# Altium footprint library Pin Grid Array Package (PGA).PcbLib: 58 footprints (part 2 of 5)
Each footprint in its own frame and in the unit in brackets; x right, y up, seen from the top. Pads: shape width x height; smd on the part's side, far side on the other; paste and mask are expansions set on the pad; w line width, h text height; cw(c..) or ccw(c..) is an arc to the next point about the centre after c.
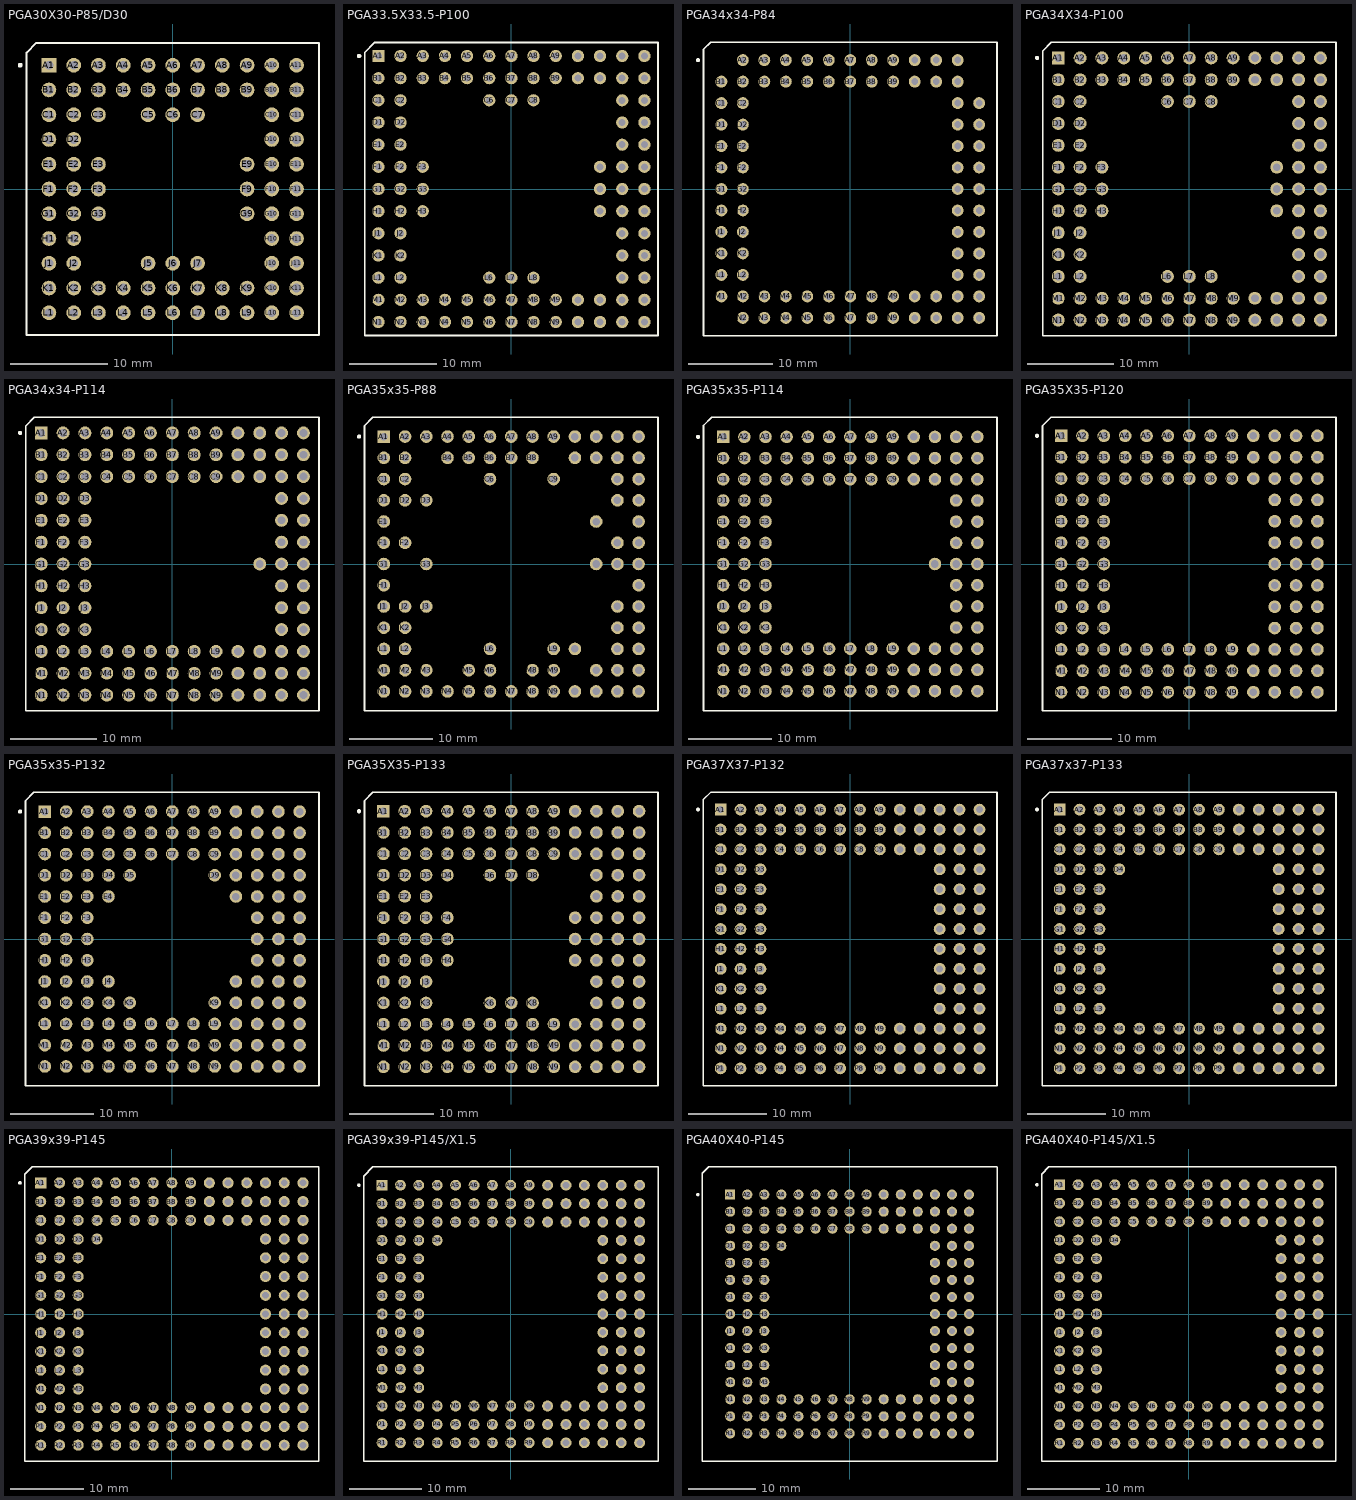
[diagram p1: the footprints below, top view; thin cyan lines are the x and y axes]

## PGA30X30-P85/D30 [mm]
pads (85):
  rect 1.5x1.5 hole 0.9: A1(-12.7,12.7)
  round 1.5 hole 0.9: A2(-10.16,12.7) A3(-7.62,12.7) A4(-5.08,12.7) A5(-2.54,12.7) A6(0,12.7) A7(2.54,12.7) A8(5.08,12.7) A9(7.62,12.7) A10(10.16,12.7) A11(12.7,12.7) B1(-12.7,10.16) B2(-10.16,10.16) B3(-7.62,10.16) B4(-5.08,10.16) B5(-2.54,10.16) B6(0,10.16) B7(2.54,10.16) B8(5.08,10.16) B9(7.62,10.16) B10(10.16,10.16) B11(12.7,10.16) C1(-12.7,7.62) C2(-10.16,7.62) C3(-7.62,7.62) C5(-2.54,7.62) C6(0,7.62) C7(2.54,7.62) C10(10.16,7.62) C11(12.7,7.62) D1(-12.7,5.08) D2(-10.16,5.08) D10(10.16,5.08) D11(12.7,5.08) E1(-12.7,2.54) E2(-10.16,2.54) E3(-7.62,2.54) E9(7.62,2.54) E10(10.16,2.54) E11(12.7,2.54) F1(-12.7,0) F2(-10.16,0) F3(-7.62,0) F9(7.62,0) F10(10.16,0) F11(12.7,0) G1(-12.7,-2.54) G2(-10.16,-2.54) G3(-7.62,-2.54) G9(7.62,-2.54) G10(10.16,-2.54) G11(12.7,-2.54) H1(-12.7,-5.08) H2(-10.16,-5.08) H10(10.16,-5.08) H11(12.7,-5.08) J1(-12.7,-7.62) J2(-10.16,-7.62) J5(-2.54,-7.62) J6(0,-7.62) J7(2.54,-7.62) J10(10.16,-7.62) J11(12.7,-7.62) K1(-12.7,-10.16) K2(-10.16,-10.16) K3(-7.62,-10.16) K4(-5.08,-10.16) K5(-2.54,-10.16) K6(0,-10.16) K7(2.54,-10.16) K8(5.08,-10.16) K9(7.62,-10.16) K10(10.16,-10.16) K11(12.7,-10.16) L1(-12.7,-12.7) L2(-10.16,-12.7) L3(-7.62,-12.7) L4(-5.08,-12.7) L5(-2.54,-12.7) L6(0,-12.7) L7(2.54,-12.7) L8(5.08,-12.7) L9(7.62,-12.7) L10(10.16,-12.7) L11(12.7,-12.7)
Top Overlay:
  circle w0.25: c-15.65,12.7 r0.125
  lines w0.2: -15,-15 -15,14 -14,15 15,15 15,-15 -15,-15

## PGA33.5X33.5-P100 [mm]
pads (100):
  rect 1.4x1.4 hole 0.8: A1(-15.24,15.24)
  round 1.4 hole 0.8: A2(-12.7,15.24) A3(-10.16,15.24) A4(-7.62,15.24) A5(-5.08,15.24) A6(-2.54,15.24) A7(0,15.24) A8(2.54,15.24) A9(5.08,15.24) A10(7.62,15.24) A11(10.16,15.24) A12(12.7,15.24) A13(15.24,15.24) B1(-15.24,12.7) B2(-12.7,12.7) B3(-10.16,12.7) B4(-7.62,12.7) B5(-5.08,12.7) B6(-2.54,12.7) B7(0,12.7) B8(2.54,12.7) B9(5.08,12.7) B10(7.62,12.7) B11(10.16,12.7) B12(12.7,12.7) B13(15.24,12.7) C1(-15.24,10.16) C2(-12.7,10.16) C6(-2.54,10.16) C7(0,10.16) C8(2.54,10.16) C12(12.7,10.16) C13(15.24,10.16) D1(-15.24,7.62) D2(-12.7,7.62) D12(12.7,7.62) D13(15.24,7.62) E1(-15.24,5.08) E2(-12.7,5.08) E12(12.7,5.08) E13(15.24,5.08) F1(-15.24,2.54) F2(-12.7,2.54) F3(-10.16,2.54) F11(10.16,2.54) F12(12.7,2.54) F13(15.24,2.54) G1(-15.24,0) G2(-12.7,0) G3(-10.16,0) G11(10.16,0) G12(12.7,0) G13(15.24,0) H1(-15.24,-2.54) H2(-12.7,-2.54) H3(-10.16,-2.54) H11(10.16,-2.54) H12(12.7,-2.54) H13(15.24,-2.54) J1(-15.24,-5.08) J2(-12.7,-5.08) J12(12.7,-5.08) J13(15.24,-5.08) K1(-15.24,-7.62) K2(-12.7,-7.62) K12(12.7,-7.62) K13(15.24,-7.62) L1(-15.24,-10.16) L2(-12.7,-10.16) L6(-2.54,-10.16) L7(0,-10.16) L8(2.54,-10.16) L12(12.7,-10.16) L13(15.24,-10.16) M1(-15.24,-12.7) M2(-12.7,-12.7) M3(-10.16,-12.7) M4(-7.62,-12.7) M5(-5.08,-12.7) M6(-2.54,-12.7) M7(0,-12.7) M8(2.54,-12.7) M9(5.08,-12.7) M10(7.62,-12.7) M11(10.16,-12.7) M12(12.7,-12.7) M13(15.24,-12.7) N1(-15.24,-15.24) N2(-12.7,-15.24) N3(-10.16,-15.24) N4(-7.62,-15.24) N5(-5.08,-15.24) N6(-2.54,-15.24) N7(0,-15.24) N8(2.54,-15.24) N9(5.08,-15.24) N10(7.62,-15.24) N11(10.16,-15.24) N12(12.7,-15.24) N13(15.24,-15.24)
Top Overlay:
  circle w0.25: c-17.45,15.24 r0.125
  lines w0.2: -16.8,-16.8 -16.8,15.646 -15.646,16.8 16.8,16.8 16.8,-16.8 -16.8,-16.8

## PGA34x34-P84 [mm]
pads (84):
  round 1.4 hole 0.8: A2(-12.7,15.24) A3(-10.16,15.24) A4(-7.62,15.24) A5(-5.08,15.24) A6(-2.54,15.24) A7(0,15.24) A8(2.54,15.24) A9(5.08,15.24) A10(7.62,15.24) A11(10.16,15.24) A12(12.7,15.24) B1(-15.24,12.7) B2(-12.7,12.7) B3(-10.16,12.7) B4(-7.62,12.7) B5(-5.08,12.7) B6(-2.54,12.7) B7(0,12.7) B8(2.54,12.7) B9(5.08,12.7) B10(7.62,12.7) B11(10.16,12.7) B12(12.7,12.7) C1(-15.24,10.16) C2(-12.7,10.16) C12(12.7,10.16) C13(15.24,10.16) D1(-15.24,7.62) D2(-12.7,7.62) D12(12.7,7.62) D13(15.24,7.62) E1(-15.24,5.08) E2(-12.7,5.08) E12(12.7,5.08) E13(15.24,5.08) F1(-15.24,2.54) F2(-12.7,2.54) F12(12.7,2.54) F13(15.24,2.54) G1(-15.24,0) G2(-12.7,0) G12(12.7,0) G13(15.24,0) H1(-15.24,-2.54) H2(-12.7,-2.54) H12(12.7,-2.54) H13(15.24,-2.54) J1(-15.24,-5.08) J2(-12.7,-5.08) J12(12.7,-5.08) J13(15.24,-5.08) K1(-15.24,-7.62) K2(-12.7,-7.62) K12(12.7,-7.62) K13(15.24,-7.62) L1(-15.24,-10.16) L2(-12.7,-10.16) L12(12.7,-10.16) L13(15.24,-10.16) M1(-15.24,-12.7) M2(-12.7,-12.7) M3(-10.16,-12.7) M4(-7.62,-12.7) M5(-5.08,-12.7) M6(-2.54,-12.7) M7(0,-12.7) M8(2.54,-12.7) M9(5.08,-12.7) M10(7.62,-12.7) M11(10.16,-12.7) M12(12.7,-12.7) M13(15.24,-12.7) N2(-12.7,-15.24) N3(-10.16,-15.24) N4(-7.62,-15.24) N5(-5.08,-15.24) N6(-2.54,-15.24) N7(0,-15.24) N8(2.54,-15.24) N9(5.08,-15.24) N10(7.62,-15.24) N11(10.16,-15.24) N12(12.7,-15.24) N13(15.24,-15.24)
Top Overlay:
  circle w0.25: c-18,15.24 r0.125
  lines w0.2: -17.35,-17.35 17.35,-17.35 17.35,17.35 -16.51,17.35 -17.35,16.51 -17.35,-17.35

## PGA34X34-P100 [mm]
pads (100):
  rect 1.5x1.5 hole 0.9: A1(-15.24,15.24)
  round 1.5 hole 0.9: A2(-12.7,15.24) A3(-10.16,15.24) A4(-7.62,15.24) A5(-5.08,15.24) A6(-2.54,15.24) A7(0,15.24) A8(2.54,15.24) A9(5.08,15.24) A10(7.62,15.24) A11(10.16,15.24) A12(12.7,15.24) A13(15.24,15.24) B1(-15.24,12.7) B2(-12.7,12.7) B3(-10.16,12.7) B4(-7.62,12.7) B5(-5.08,12.7) B6(-2.54,12.7) B7(0,12.7) B8(2.54,12.7) B9(5.08,12.7) B10(7.62,12.7) B11(10.16,12.7) B12(12.7,12.7) B13(15.24,12.7) C1(-15.24,10.16) C2(-12.7,10.16) C6(-2.54,10.16) C7(0,10.16) C8(2.54,10.16) C12(12.7,10.16) C13(15.24,10.16) D1(-15.24,7.62) D2(-12.7,7.62) D12(12.7,7.62) D13(15.24,7.62) E1(-15.24,5.08) E2(-12.7,5.08) E12(12.7,5.08) E13(15.24,5.08) F1(-15.24,2.54) F2(-12.7,2.54) F3(-10.16,2.54) F11(10.16,2.54) F12(12.7,2.54) F13(15.24,2.54) G1(-15.24,0) G2(-12.7,0) G3(-10.16,0) G11(10.16,0) G12(12.7,0) G13(15.24,0) H1(-15.24,-2.54) H2(-12.7,-2.54) H3(-10.16,-2.54) H11(10.16,-2.54) H12(12.7,-2.54) H13(15.24,-2.54) J1(-15.24,-5.08) J2(-12.7,-5.08) J12(12.7,-5.08) J13(15.24,-5.08) K1(-15.24,-7.62) K2(-12.7,-7.62) K12(12.7,-7.62) K13(15.24,-7.62) L1(-15.24,-10.16) L2(-12.7,-10.16) L6(-2.54,-10.16) L7(0,-10.16) L8(2.54,-10.16) L12(12.7,-10.16) L13(15.24,-10.16) M1(-15.24,-12.7) M2(-12.7,-12.7) M3(-10.16,-12.7) M4(-7.62,-12.7) M5(-5.08,-12.7) M6(-2.54,-12.7) M7(0,-12.7) M8(2.54,-12.7) M9(5.08,-12.7) M10(7.62,-12.7) M11(10.16,-12.7) M12(12.7,-12.7) M13(15.24,-12.7) N1(-15.24,-15.24) N2(-12.7,-15.24) N3(-10.16,-15.24) N4(-7.62,-15.24) N5(-5.08,-15.24) N6(-2.54,-15.24) N7(0,-15.24) N8(2.54,-15.24) N9(5.08,-15.24) N10(7.62,-15.24) N11(10.16,-15.24) N12(12.7,-15.24) N13(15.24,-15.24)
Top Overlay:
  circle w0.25: c-17.7,15.24 r0.125
  lines w0.2: -17.05,-17.05 -17.05,16.05 -16.05,17.05 17.05,17.05 17.05,-17.05 -17.05,-17.05

## PGA34x34-P114 [mm]
pads (114):
  rect 1.5x1.5 hole 0.9: A1(-15.24,15.24)
  round 1.5 hole 0.9: A2(-12.7,15.24) A3(-10.16,15.24) A4(-7.62,15.24) A5(-5.08,15.24) A6(-2.54,15.24) A7(0,15.24) A8(2.54,15.24) A9(5.08,15.24) A10(7.62,15.24) A11(10.16,15.24) A12(12.7,15.24) A13(15.24,15.24) B1(-15.24,12.7) B2(-12.7,12.7) B3(-10.16,12.7) B4(-7.62,12.7) B5(-5.08,12.7) B6(-2.54,12.7) B7(0,12.7) B8(2.54,12.7) B9(5.08,12.7) B10(7.62,12.7) B11(10.16,12.7) B12(12.7,12.7) B13(15.24,12.7) C1(-15.24,10.16) C2(-12.7,10.16) C3(-10.16,10.16) C4(-7.62,10.16) C5(-5.08,10.16) C6(-2.54,10.16) C7(0,10.16) C8(2.54,10.16) C9(5.08,10.16) C10(7.62,10.16) C11(10.16,10.16) C12(12.7,10.16) C13(15.24,10.16) D1(-15.24,7.62) D2(-12.7,7.62) D3(-10.16,7.62) D12(12.7,7.62) D13(15.24,7.62) E1(-15.24,5.08) E2(-12.7,5.08) E3(-10.16,5.08) E12(12.7,5.08) E13(15.24,5.08) F1(-15.24,2.54) F2(-12.7,2.54) F3(-10.16,2.54) F12(12.7,2.54) F13(15.24,2.54) G1(-15.24,0) G2(-12.7,0) G3(-10.16,0) G11(10.16,0) G12(12.7,0) G13(15.24,0) H1(-15.24,-2.54) H2(-12.7,-2.54) H3(-10.16,-2.54) H12(12.7,-2.54) H13(15.24,-2.54) J1(-15.24,-5.08) J2(-12.7,-5.08) J3(-10.16,-5.08) J12(12.7,-5.08) J13(15.24,-5.08) K1(-15.24,-7.62) K2(-12.7,-7.62) K3(-10.16,-7.62) K12(12.7,-7.62) K13(15.24,-7.62) L1(-15.24,-10.16) L2(-12.7,-10.16) L3(-10.16,-10.16) L4(-7.62,-10.16) L5(-5.08,-10.16) L6(-2.54,-10.16) L7(0,-10.16) L8(2.54,-10.16) L9(5.08,-10.16) L10(7.62,-10.16) L11(10.16,-10.16) L12(12.7,-10.16) L13(15.24,-10.16) M1(-15.24,-12.7) M2(-12.7,-12.7) M3(-10.16,-12.7) M4(-7.62,-12.7) M5(-5.08,-12.7) M6(-2.54,-12.7) M7(0,-12.7) M8(2.54,-12.7) M9(5.08,-12.7) M10(7.62,-12.7) M11(10.16,-12.7) M12(12.7,-12.7) M13(15.24,-12.7) N1(-15.24,-15.24) N2(-12.7,-15.24) N3(-10.16,-15.24) N4(-7.62,-15.24) N5(-5.08,-15.24) N6(-2.54,-15.24) N7(0,-15.24) N8(2.54,-15.24) N9(5.08,-15.24) N10(7.62,-15.24) N11(10.16,-15.24) N12(12.7,-15.24) N13(15.24,-15.24)
Top Overlay:
  circle w0.25: c-17.7,15.24 r0.125
  lines w0.2: -17.05,-17.05 17.05,-17.05 17.05,17.05 -16.05,17.05 -17.05,16.05 -17.05,-17.05

## PGA35x35-P88 [mm]
pads (88):
  rect 1.5x1.5 hole 0.9: A1(-15.24,15.24)
  round 1.5 hole 0.9: A2(-12.7,15.24) A3(-10.16,15.24) A4(-7.62,15.24) A5(-5.08,15.24) A6(-2.54,15.24) A7(0,15.24) A8(2.54,15.24) A9(5.08,15.24) A10(7.62,15.24) A11(10.16,15.24) A12(12.7,15.24) A13(15.24,15.24) B1(-15.24,12.7) B2(-12.7,12.7) B4(-7.62,12.7) B5(-5.08,12.7) B6(-2.54,12.7) B7(0,12.7) B8(2.54,12.7) B10(7.62,12.7) B11(10.16,12.7) B12(12.7,12.7) B13(15.24,12.7) C1(-15.24,10.16) C2(-12.7,10.16) C6(-2.54,10.16) C9(5.08,10.16) C12(12.7,10.16) C13(15.24,10.16) D1(-15.24,7.62) D2(-12.7,7.62) D3(-10.16,7.62) D12(12.7,7.62) D13(15.24,7.62) E1(-15.24,5.08) E11(10.16,5.08) E13(15.24,5.08) F1(-15.24,2.54) F2(-12.7,2.54) F12(12.7,2.54) F13(15.24,2.54) G1(-15.24,0) G3(-10.16,0) G11(10.16,0) G12(12.7,0) G13(15.24,0) H1(-15.24,-2.54) H13(15.24,-2.54) J1(-15.24,-5.08) J2(-12.7,-5.08) J3(-10.16,-5.08) J12(12.7,-5.08) J13(15.24,-5.08) K1(-15.24,-7.62) K2(-12.7,-7.62) K12(12.7,-7.62) K13(15.24,-7.62) L1(-15.24,-10.16) L2(-12.7,-10.16) L6(-2.54,-10.16) L9(5.08,-10.16) L10(7.62,-10.16) L12(12.7,-10.16) L13(15.24,-10.16) M1(-15.24,-12.7) M2(-12.7,-12.7) M3(-10.16,-12.7) M5(-5.08,-12.7) M6(-2.54,-12.7) M8(2.54,-12.7) M9(5.08,-12.7) M11(10.16,-12.7) M12(12.7,-12.7) M13(15.24,-12.7) N1(-15.24,-15.24) N2(-12.7,-15.24) N3(-10.16,-15.24) N4(-7.62,-15.24) N5(-5.08,-15.24) N6(-2.54,-15.24) N7(0,-15.24) N8(2.54,-15.24) N9(5.08,-15.24) N10(7.62,-15.24) N11(10.16,-15.24) N12(12.7,-15.24) N13(15.24,-15.24)
Top Overlay:
  circle w0.25: c-18.2,15.24 r0.125
  lines w0.2: -17.55,-17.55 17.55,-17.55 17.55,17.55 -16.55,17.55 -17.55,16.55 -17.55,-17.55

## PGA35x35-P114 [mm]
pads (114):
  rect 1.5x1.5 hole 0.9: A1(-15.24,15.24)
  round 1.5 hole 0.9: A2(-12.7,15.24) A3(-10.16,15.24) A4(-7.62,15.24) A5(-5.08,15.24) A6(-2.54,15.24) A7(0,15.24) A8(2.54,15.24) A9(5.08,15.24) A10(7.62,15.24) A11(10.16,15.24) A12(12.7,15.24) A13(15.24,15.24) B1(-15.24,12.7) B2(-12.7,12.7) B3(-10.16,12.7) B4(-7.62,12.7) B5(-5.08,12.7) B6(-2.54,12.7) B7(0,12.7) B8(2.54,12.7) B9(5.08,12.7) B10(7.62,12.7) B11(10.16,12.7) B12(12.7,12.7) B13(15.24,12.7) C1(-15.24,10.16) C2(-12.7,10.16) C3(-10.16,10.16) C4(-7.62,10.16) C5(-5.08,10.16) C6(-2.54,10.16) C7(0,10.16) C8(2.54,10.16) C9(5.08,10.16) C10(7.62,10.16) C11(10.16,10.16) C12(12.7,10.16) C13(15.24,10.16) D1(-15.24,7.62) D2(-12.7,7.62) D3(-10.16,7.62) D12(12.7,7.62) D13(15.24,7.62) E1(-15.24,5.08) E2(-12.7,5.08) E3(-10.16,5.08) E12(12.7,5.08) E13(15.24,5.08) F1(-15.24,2.54) F2(-12.7,2.54) F3(-10.16,2.54) F12(12.7,2.54) F13(15.24,2.54) G1(-15.24,0) G2(-12.7,0) G3(-10.16,0) G11(10.16,0) G12(12.7,0) G13(15.24,0) H1(-15.24,-2.54) H2(-12.7,-2.54) H3(-10.16,-2.54) H12(12.7,-2.54) H13(15.24,-2.54) J1(-15.24,-5.08) J2(-12.7,-5.08) J3(-10.16,-5.08) J12(12.7,-5.08) J13(15.24,-5.08) K1(-15.24,-7.62) K2(-12.7,-7.62) K3(-10.16,-7.62) K12(12.7,-7.62) K13(15.24,-7.62) L1(-15.24,-10.16) L2(-12.7,-10.16) L3(-10.16,-10.16) L4(-7.62,-10.16) L5(-5.08,-10.16) L6(-2.54,-10.16) L7(0,-10.16) L8(2.54,-10.16) L9(5.08,-10.16) L10(7.62,-10.16) L11(10.16,-10.16) L12(12.7,-10.16) L13(15.24,-10.16) M1(-15.24,-12.7) M2(-12.7,-12.7) M3(-10.16,-12.7) M4(-7.62,-12.7) M5(-5.08,-12.7) M6(-2.54,-12.7) M7(0,-12.7) M8(2.54,-12.7) M9(5.08,-12.7) M10(7.62,-12.7) M11(10.16,-12.7) M12(12.7,-12.7) M13(15.24,-12.7) N1(-15.24,-15.24) N2(-12.7,-15.24) N3(-10.16,-15.24) N4(-7.62,-15.24) N5(-5.08,-15.24) N6(-2.54,-15.24) N7(0,-15.24) N8(2.54,-15.24) N9(5.08,-15.24) N10(7.62,-15.24) N11(10.16,-15.24) N12(12.7,-15.24) N13(15.24,-15.24)
Top Overlay:
  circle w0.25: c-18.25,15.24 r0.125
  lines w0.2: -17.6,-17.6 17.6,-17.6 17.6,17.6 -16.6,17.6 -17.6,16.6 -17.6,-17.6

## PGA35X35-P120 [mm]
pads (120):
  rect 1.5x1.5 hole 0.9: A1(-15.24,15.24)
  round 1.5 hole 0.9: A2(-12.7,15.24) A3(-10.16,15.24) A4(-7.62,15.24) A5(-5.08,15.24) A6(-2.54,15.24) A7(0,15.24) A8(2.54,15.24) A9(5.08,15.24) A10(7.62,15.24) A11(10.16,15.24) A12(12.7,15.24) A13(15.24,15.24) B1(-15.24,12.7) B2(-12.7,12.7) B3(-10.16,12.7) B4(-7.62,12.7) B5(-5.08,12.7) B6(-2.54,12.7) B7(0,12.7) B8(2.54,12.7) B9(5.08,12.7) B10(7.62,12.7) B11(10.16,12.7) B12(12.7,12.7) B13(15.24,12.7) C1(-15.24,10.16) C2(-12.7,10.16) C3(-10.16,10.16) C4(-7.62,10.16) C5(-5.08,10.16) C6(-2.54,10.16) C7(0,10.16) C8(2.54,10.16) C9(5.08,10.16) C10(7.62,10.16) C11(10.16,10.16) C12(12.7,10.16) C13(15.24,10.16) D1(-15.24,7.62) D2(-12.7,7.62) D3(-10.16,7.62) D11(10.16,7.62) D12(12.7,7.62) D13(15.24,7.62) E1(-15.24,5.08) E2(-12.7,5.08) E3(-10.16,5.08) E11(10.16,5.08) E12(12.7,5.08) E13(15.24,5.08) F1(-15.24,2.54) F2(-12.7,2.54) F3(-10.16,2.54) F11(10.16,2.54) F12(12.7,2.54) F13(15.24,2.54) G1(-15.24,0) G2(-12.7,0) G3(-10.16,0) G11(10.16,0) G12(12.7,0) G13(15.24,0) H1(-15.24,-2.54) H2(-12.7,-2.54) H3(-10.16,-2.54) H11(10.16,-2.54) H12(12.7,-2.54) H13(15.24,-2.54) J1(-15.24,-5.08) J2(-12.7,-5.08) J3(-10.16,-5.08) J11(10.16,-5.08) J12(12.7,-5.08) J13(15.24,-5.08) K1(-15.24,-7.62) K2(-12.7,-7.62) K3(-10.16,-7.62) K11(10.16,-7.62) K12(12.7,-7.62) K13(15.24,-7.62) L1(-15.24,-10.16) L2(-12.7,-10.16) L3(-10.16,-10.16) L4(-7.62,-10.16) L5(-5.08,-10.16) L6(-2.54,-10.16) L7(0,-10.16) L8(2.54,-10.16) L9(5.08,-10.16) L10(7.62,-10.16) L11(10.16,-10.16) L12(12.7,-10.16) L13(15.24,-10.16) M1(-15.24,-12.7) M2(-12.7,-12.7) M3(-10.16,-12.7) M4(-7.62,-12.7) M5(-5.08,-12.7) M6(-2.54,-12.7) M7(0,-12.7) M8(2.54,-12.7) M9(5.08,-12.7) M10(7.62,-12.7) M11(10.16,-12.7) M12(12.7,-12.7) M13(15.24,-12.7) N1(-15.24,-15.24) N2(-12.7,-15.24) N3(-10.16,-15.24) N4(-7.62,-15.24) N5(-5.08,-15.24) N6(-2.54,-15.24) N7(0,-15.24) N8(2.54,-15.24) N9(5.08,-15.24) N10(7.62,-15.24) N11(10.16,-15.24) N12(12.7,-15.24) N13(15.24,-15.24)
Top Overlay:
  circle w0.25: c-18.1,15.24 r0.125
  lines w0.2: -17.45,-17.45 17.45,-17.45 17.45,17.45 -16.45,17.45 -17.45,16.45 -17.45,-17.45

## PGA35x35-P132 [mm]
pads (132):
  rect 1.5x1.5 hole 0.9: A1(-15.24,15.24)
  round 1.5 hole 0.9: A2(-12.7,15.24) A3(-10.16,15.24) A4(-7.62,15.24) A5(-5.08,15.24) A6(-2.54,15.24) A7(0,15.24) A8(2.54,15.24) A9(5.08,15.24) A10(7.62,15.24) A11(10.16,15.24) A12(12.7,15.24) A13(15.24,15.24) B1(-15.24,12.7) B2(-12.7,12.7) B3(-10.16,12.7) B4(-7.62,12.7) B5(-5.08,12.7) B6(-2.54,12.7) B7(0,12.7) B8(2.54,12.7) B9(5.08,12.7) B10(7.62,12.7) B11(10.16,12.7) B12(12.7,12.7) B13(15.24,12.7) C1(-15.24,10.16) C2(-12.7,10.16) C3(-10.16,10.16) C4(-7.62,10.16) C5(-5.08,10.16) C6(-2.54,10.16) C7(0,10.16) C8(2.54,10.16) C9(5.08,10.16) C10(7.62,10.16) C11(10.16,10.16) C12(12.7,10.16) C13(15.24,10.16) D1(-15.24,7.62) D2(-12.7,7.62) D3(-10.16,7.62) D4(-7.62,7.62) D5(-5.08,7.62) D9(5.08,7.62) D10(7.62,7.62) D11(10.16,7.62) D12(12.7,7.62) D13(15.24,7.62) E1(-15.24,5.08) E2(-12.7,5.08) E3(-10.16,5.08) E4(-7.62,5.08) E10(7.62,5.08) E11(10.16,5.08) E12(12.7,5.08) E13(15.24,5.08) F1(-15.24,2.54) F2(-12.7,2.54) F3(-10.16,2.54) F11(10.16,2.54) F12(12.7,2.54) F13(15.24,2.54) G1(-15.24,0) G2(-12.7,0) G3(-10.16,0) G11(10.16,0) G12(12.7,0) G13(15.24,0) H1(-15.24,-2.54) H2(-12.7,-2.54) H3(-10.16,-2.54) H11(10.16,-2.54) H12(12.7,-2.54) H13(15.24,-2.54) J1(-15.24,-5.08) J2(-12.7,-5.08) J3(-10.16,-5.08) J4(-7.62,-5.08) J10(7.62,-5.08) J11(10.16,-5.08) J12(12.7,-5.08) J13(15.24,-5.08) K1(-15.24,-7.62) K2(-12.7,-7.62) K3(-10.16,-7.62) K4(-7.62,-7.62) K5(-5.08,-7.62) K9(5.08,-7.62) K10(7.62,-7.62) K11(10.16,-7.62) K12(12.7,-7.62) K13(15.24,-7.62) L1(-15.24,-10.16) L2(-12.7,-10.16) L3(-10.16,-10.16) L4(-7.62,-10.16) L5(-5.08,-10.16) L6(-2.54,-10.16) L7(0,-10.16) L8(2.54,-10.16) L9(5.08,-10.16) L10(7.62,-10.16) L11(10.16,-10.16) L12(12.7,-10.16) L13(15.24,-10.16) M1(-15.24,-12.7) M2(-12.7,-12.7) M3(-10.16,-12.7) M4(-7.62,-12.7) M5(-5.08,-12.7) M6(-2.54,-12.7) M7(0,-12.7) M8(2.54,-12.7) M9(5.08,-12.7) M10(7.62,-12.7) M11(10.16,-12.7) M12(12.7,-12.7) M13(15.24,-12.7) N1(-15.24,-15.24) N2(-12.7,-15.24) N3(-10.16,-15.24) N4(-7.62,-15.24) N5(-5.08,-15.24) N6(-2.54,-15.24) N7(0,-15.24) N8(2.54,-15.24) N9(5.08,-15.24) N10(7.62,-15.24) N11(10.16,-15.24) N12(12.7,-15.24) N13(15.24,-15.24)
Top Overlay:
  circle w0.25: c-18.2,15.24 r0.125
  lines w0.2: -17.55,-17.55 17.55,-17.55 17.55,17.55 -16.55,17.55 -17.55,16.55 -17.55,-17.55

## PGA35X35-P133 [mm]
pads (133):
  rect 1.5x1.5 hole 0.9: A1(-15.24,15.24)
  round 1.5 hole 0.9: A2(-12.7,15.24) A3(-10.16,15.24) A4(-7.62,15.24) A5(-5.08,15.24) A6(-2.54,15.24) A7(0,15.24) A8(2.54,15.24) A9(5.08,15.24) A10(7.62,15.24) A11(10.16,15.24) A12(12.7,15.24) A13(15.24,15.24) B1(-15.24,12.7) B2(-12.7,12.7) B3(-10.16,12.7) B4(-7.62,12.7) B5(-5.08,12.7) B6(-2.54,12.7) B7(0,12.7) B8(2.54,12.7) B9(5.08,12.7) B10(7.62,12.7) B11(10.16,12.7) B12(12.7,12.7) B13(15.24,12.7) C1(-15.24,10.16) C2(-12.7,10.16) C3(-10.16,10.16) C4(-7.62,10.16) C5(-5.08,10.16) C6(-2.54,10.16) C7(0,10.16) C8(2.54,10.16) C9(5.08,10.16) C10(7.62,10.16) C11(10.16,10.16) C12(12.7,10.16) C13(15.24,10.16) D1(-15.24,7.62) D2(-12.7,7.62) D3(-10.16,7.62) D4(-7.62,7.62) D6(-2.54,7.62) D7(0,7.62) D8(2.54,7.62) D11(10.16,7.62) D12(12.7,7.62) D13(15.24,7.62) E1(-15.24,5.08) E2(-12.7,5.08) E3(-10.16,5.08) E11(10.16,5.08) E12(12.7,5.08) E13(15.24,5.08) F1(-15.24,2.54) F2(-12.7,2.54) F3(-10.16,2.54) F4(-7.62,2.54) F10(7.62,2.54) F11(10.16,2.54) F12(12.7,2.54) F13(15.24,2.54) G1(-15.24,0) G2(-12.7,0) G3(-10.16,0) G4(-7.62,0) G10(7.62,0) G11(10.16,0) G12(12.7,0) G13(15.24,0) H1(-15.24,-2.54) H2(-12.7,-2.54) H3(-10.16,-2.54) H4(-7.62,-2.54) H10(7.62,-2.54) H11(10.16,-2.54) H12(12.7,-2.54) H13(15.24,-2.54) J1(-15.24,-5.08) J2(-12.7,-5.08) J3(-10.16,-5.08) J11(10.16,-5.08) J12(12.7,-5.08) J13(15.24,-5.08) K1(-15.24,-7.62) K2(-12.7,-7.62) K3(-10.16,-7.62) K6(-2.54,-7.62) K7(0,-7.62) K8(2.54,-7.62) K11(10.16,-7.62) K12(12.7,-7.62) K13(15.24,-7.62) L1(-15.24,-10.16) L2(-12.7,-10.16) L3(-10.16,-10.16) L4(-7.62,-10.16) L5(-5.08,-10.16) L6(-2.54,-10.16) L7(0,-10.16) L8(2.54,-10.16) L9(5.08,-10.16) L10(7.62,-10.16) L11(10.16,-10.16) L12(12.7,-10.16) L13(15.24,-10.16) M1(-15.24,-12.7) M2(-12.7,-12.7) M3(-10.16,-12.7) M4(-7.62,-12.7) M5(-5.08,-12.7) M6(-2.54,-12.7) M7(0,-12.7) M8(2.54,-12.7) M9(5.08,-12.7) M10(7.62,-12.7) M11(10.16,-12.7) M12(12.7,-12.7) M13(15.24,-12.7) N1(-15.24,-15.24) N2(-12.7,-15.24) N3(-10.16,-15.24) N4(-7.62,-15.24) N5(-5.08,-15.24) N6(-2.54,-15.24) N7(0,-15.24) N8(2.54,-15.24) N9(5.08,-15.24) N10(7.62,-15.24) N11(10.16,-15.24) N12(12.7,-15.24) N13(15.24,-15.24)
Top Overlay:
  circle w0.25: c-18.15,15.24 r0.125
  lines w0.2: -17.5,-17.5 -17.5,16.5 -16.5,17.5 17.5,17.5 17.5,-17.5 -17.5,-17.5

## PGA37X37-P132 [mm]
pads (132):
  rect 1.5x1.5 hole 0.9: A1(-16.51,16.51)
  round 1.5 hole 0.9: A2(-13.97,16.51) A3(-11.43,16.51) A4(-8.89,16.51) A5(-6.35,16.51) A6(-3.81,16.51) A7(-1.27,16.51) A8(1.27,16.51) A9(3.81,16.51) A10(6.35,16.51) A11(8.89,16.51) A12(11.43,16.51) A13(13.97,16.51) A14(16.51,16.51) B1(-16.51,13.97) B2(-13.97,13.97) B3(-11.43,13.97) B4(-8.89,13.97) B5(-6.35,13.97) B6(-3.81,13.97) B7(-1.27,13.97) B8(1.27,13.97) B9(3.81,13.97) B10(6.35,13.97) B11(8.89,13.97) B12(11.43,13.97) B13(13.97,13.97) B14(16.51,13.97) C1(-16.51,11.43) C2(-13.97,11.43) C3(-11.43,11.43) C4(-8.89,11.43) C5(-6.35,11.43) C6(-3.81,11.43) C7(-1.27,11.43) C8(1.27,11.43) C9(3.81,11.43) C10(6.35,11.43) C11(8.89,11.43) C12(11.43,11.43) C13(13.97,11.43) C14(16.51,11.43) D1(-16.51,8.89) D2(-13.97,8.89) D3(-11.43,8.89) D12(11.43,8.89) D13(13.97,8.89) D14(16.51,8.89) E1(-16.51,6.35) E2(-13.97,6.35) E3(-11.43,6.35) E12(11.43,6.35) E13(13.97,6.35) E14(16.51,6.35) F1(-16.51,3.81) F2(-13.97,3.81) F3(-11.43,3.81) F12(11.43,3.81) F13(13.97,3.81) F14(16.51,3.81) G1(-16.51,1.27) G2(-13.97,1.27) G3(-11.43,1.27) G12(11.43,1.27) G13(13.97,1.27) G14(16.51,1.27) H1(-16.51,-1.27) H2(-13.97,-1.27) H3(-11.43,-1.27) H12(11.43,-1.27) H13(13.97,-1.27) H14(16.51,-1.27) J1(-16.51,-3.81) J2(-13.97,-3.81) J3(-11.43,-3.81) J12(11.43,-3.81) J13(13.97,-3.81) J14(16.51,-3.81) K1(-16.51,-6.35) K2(-13.97,-6.35) K3(-11.43,-6.35) K12(11.43,-6.35) K13(13.97,-6.35) K14(16.51,-6.35) L1(-16.51,-8.89) L2(-13.97,-8.89) L3(-11.43,-8.89) L12(11.43,-8.89) L13(13.97,-8.89) L14(16.51,-8.89) M1(-16.51,-11.43) M2(-13.97,-11.43) M3(-11.43,-11.43) M4(-8.89,-11.43) M5(-6.35,-11.43) M6(-3.81,-11.43) M7(-1.27,-11.43) M8(1.27,-11.43) M9(3.81,-11.43) M10(6.35,-11.43) M11(8.89,-11.43) M12(11.43,-11.43) M13(13.97,-11.43) M14(16.51,-11.43) N1(-16.51,-13.97) N2(-13.97,-13.97) N3(-11.43,-13.97) N4(-8.89,-13.97) N5(-6.35,-13.97) N6(-3.81,-13.97) N7(-1.27,-13.97) N8(1.27,-13.97) N9(3.81,-13.97) N10(6.35,-13.97) N11(8.89,-13.97) N12(11.43,-13.97) N13(13.97,-13.97) N14(16.51,-13.97) P1(-16.51,-16.51) P2(-13.97,-16.51) P3(-11.43,-16.51) P4(-8.89,-16.51) P5(-6.35,-16.51) P6(-3.81,-16.51) P7(-1.27,-16.51) P8(1.27,-16.51) P9(3.81,-16.51) P10(6.35,-16.51) P11(8.89,-16.51) P12(11.43,-16.51) P13(13.97,-16.51) P14(16.51,-16.51)
Top Overlay:
  circle w0.25: c-19.4,16.51 r0.125
  lines w0.2: -18.75,-18.75 -18.75,17.75 -17.75,18.75 18.75,18.75 18.75,-18.75 -18.75,-18.75

## PGA37x37-P133 [mm]
pads (133):
  rect 1.5x1.5 hole 0.9: A1(-16.51,16.51)
  round 1.5 hole 0.9: A2(-13.97,16.51) A3(-11.43,16.51) A4(-8.89,16.51) A5(-6.35,16.51) A6(-3.81,16.51) A7(-1.27,16.51) A8(1.27,16.51) A9(3.81,16.51) A10(6.35,16.51) A11(8.89,16.51) A12(11.43,16.51) A13(13.97,16.51) A14(16.51,16.51) B1(-16.51,13.97) B2(-13.97,13.97) B3(-11.43,13.97) B4(-8.89,13.97) B5(-6.35,13.97) B6(-3.81,13.97) B7(-1.27,13.97) B8(1.27,13.97) B9(3.81,13.97) B10(6.35,13.97) B11(8.89,13.97) B12(11.43,13.97) B13(13.97,13.97) B14(16.51,13.97) C1(-16.51,11.43) C2(-13.97,11.43) C3(-11.43,11.43) C4(-8.89,11.43) C5(-6.35,11.43) C6(-3.81,11.43) C7(-1.27,11.43) C8(1.27,11.43) C9(3.81,11.43) C10(6.35,11.43) C11(8.89,11.43) C12(11.43,11.43) C13(13.97,11.43) C14(16.51,11.43) D1(-16.51,8.89) D2(-13.97,8.89) D3(-11.43,8.89) D4(-8.89,8.89) D12(11.43,8.89) D13(13.97,8.89) D14(16.51,8.89) E1(-16.51,6.35) E2(-13.97,6.35) E3(-11.43,6.35) E12(11.43,6.35) E13(13.97,6.35) E14(16.51,6.35) F1(-16.51,3.81) F2(-13.97,3.81) F3(-11.43,3.81) F12(11.43,3.81) F13(13.97,3.81) F14(16.51,3.81) G1(-16.51,1.27) G2(-13.97,1.27) G3(-11.43,1.27) G12(11.43,1.27) G13(13.97,1.27) G14(16.51,1.27) H1(-16.51,-1.27) H2(-13.97,-1.27) H3(-11.43,-1.27) H12(11.43,-1.27) H13(13.97,-1.27) H14(16.51,-1.27) J1(-16.51,-3.81) J2(-13.97,-3.81) J3(-11.43,-3.81) J12(11.43,-3.81) J13(13.97,-3.81) J14(16.51,-3.81) K1(-16.51,-6.35) K2(-13.97,-6.35) K3(-11.43,-6.35) K12(11.43,-6.35) K13(13.97,-6.35) K14(16.51,-6.35) L1(-16.51,-8.89) L2(-13.97,-8.89) L3(-11.43,-8.89) L12(11.43,-8.89) L13(13.97,-8.89) L14(16.51,-8.89) M1(-16.51,-11.43) M2(-13.97,-11.43) M3(-11.43,-11.43) M4(-8.89,-11.43) M5(-6.35,-11.43) M6(-3.81,-11.43) M7(-1.27,-11.43) M8(1.27,-11.43) M9(3.81,-11.43) M10(6.35,-11.43) M11(8.89,-11.43) M12(11.43,-11.43) M13(13.97,-11.43) M14(16.51,-11.43) N1(-16.51,-13.97) N2(-13.97,-13.97) N3(-11.43,-13.97) N4(-8.89,-13.97) N5(-6.35,-13.97) N6(-3.81,-13.97) N7(-1.27,-13.97) N8(1.27,-13.97) N9(3.81,-13.97) N10(6.35,-13.97) N11(8.89,-13.97) N12(11.43,-13.97) N13(13.97,-13.97) N14(16.51,-13.97) P1(-16.51,-16.51) P2(-13.97,-16.51) P3(-11.43,-16.51) P4(-8.89,-16.51) P5(-6.35,-16.51) P6(-3.81,-16.51) P7(-1.27,-16.51) P8(1.27,-16.51) P9(3.81,-16.51) P10(6.35,-16.51) P11(8.89,-16.51) P12(11.43,-16.51) P13(13.97,-16.51) P14(16.51,-16.51)
Top Overlay:
  circle w0.25: c-19.4,16.51 r0.125
  lines w0.2: -18.75,-18.75 18.75,-18.75 18.75,18.75 -17.78,18.75 -18.75,17.78 -18.75,-18.75

## PGA39x39-P145 [mm]
pads (145):
  rect 1.5x1.5 hole 0.9: A1(-17.78,17.78)
  round 1.5 hole 0.9: A2(-15.24,17.78) A3(-12.7,17.78) A4(-10.16,17.78) A5(-7.62,17.78) A6(-5.08,17.78) A7(-2.54,17.78) A8(0,17.78) A9(2.54,17.78) A10(5.08,17.78) A11(7.62,17.78) A12(10.16,17.78) A13(12.7,17.78) A14(15.24,17.78) A15(17.78,17.78) B1(-17.78,15.24) B2(-15.24,15.24) B3(-12.7,15.24) B4(-10.16,15.24) B5(-7.62,15.24) B6(-5.08,15.24) B7(-2.54,15.24) B8(0,15.24) B9(2.54,15.24) B10(5.08,15.24) B11(7.62,15.24) B12(10.16,15.24) B13(12.7,15.24) B14(15.24,15.24) B15(17.78,15.24) C1(-17.78,12.7) C2(-15.24,12.7) C3(-12.7,12.7) C4(-10.16,12.7) C5(-7.62,12.7) C6(-5.08,12.7) C7(-2.54,12.7) C8(0,12.7) C9(2.54,12.7) C10(5.08,12.7) C11(7.62,12.7) C12(10.16,12.7) C13(12.7,12.7) C14(15.24,12.7) C15(17.78,12.7) D1(-17.78,10.16) D2(-15.24,10.16) D3(-12.7,10.16) D4(-10.16,10.16) D13(12.7,10.16) D14(15.24,10.16) D15(17.78,10.16) E1(-17.78,7.62) E2(-15.24,7.62) E3(-12.7,7.62) E13(12.7,7.62) E14(15.24,7.62) E15(17.78,7.62) F1(-17.78,5.08) F2(-15.24,5.08) F3(-12.7,5.08) F13(12.7,5.08) F14(15.24,5.08) F15(17.78,5.08) G1(-17.78,2.54) G2(-15.24,2.54) G3(-12.7,2.54) G13(12.7,2.54) G14(15.24,2.54) G15(17.78,2.54) H1(-17.78,0) H2(-15.24,0) H3(-12.7,0) H13(12.7,0) H14(15.24,0) H15(17.78,0) J1(-17.78,-2.54) J2(-15.24,-2.54) J3(-12.7,-2.54) J13(12.7,-2.54) J14(15.24,-2.54) J15(17.78,-2.54) K1(-17.78,-5.08) K2(-15.24,-5.08) K3(-12.7,-5.08) K13(12.7,-5.08) K14(15.24,-5.08) K15(17.78,-5.08) L1(-17.78,-7.62) L2(-15.24,-7.62) L3(-12.7,-7.62) L13(12.7,-7.62) L14(15.24,-7.62) L15(17.78,-7.62) M1(-17.78,-10.16) M2(-15.24,-10.16) M3(-12.7,-10.16) M13(12.7,-10.16) M14(15.24,-10.16) M15(17.78,-10.16) N1(-17.78,-12.7) N2(-15.24,-12.7) N3(-12.7,-12.7) N4(-10.16,-12.7) N5(-7.62,-12.7) N6(-5.08,-12.7) N7(-2.54,-12.7) N8(0,-12.7) N9(2.54,-12.7) N10(5.08,-12.7) N11(7.62,-12.7) N12(10.16,-12.7) N13(12.7,-12.7) N14(15.24,-12.7) N15(17.78,-12.7) P1(-17.78,-15.24) P2(-15.24,-15.24) P3(-12.7,-15.24) P4(-10.16,-15.24) P5(-7.62,-15.24) P6(-5.08,-15.24) P7(-2.54,-15.24) P8(0,-15.24) P9(2.54,-15.24) P10(5.08,-15.24) P11(7.62,-15.24) P12(10.16,-15.24) P13(12.7,-15.24) P14(15.24,-15.24) P15(17.78,-15.24) R1(-17.78,-17.78) R2(-15.24,-17.78) R3(-12.7,-17.78) R4(-10.16,-17.78) R5(-7.62,-17.78) R6(-5.08,-17.78) R7(-2.54,-17.78) R8(0,-17.78) R9(2.54,-17.78) R10(5.08,-17.78) R11(7.62,-17.78) R12(10.16,-17.78) R13(12.7,-17.78) R14(15.24,-17.78) R15(17.78,-17.78)
Top Overlay:
  circle w0.25: c-20.6,17.78 r0.125
  lines w0.2: -19.95,-19.95 19.95,-19.95 19.95,19.95 -18.95,19.95 -19.95,18.95 -19.95,-19.95

## PGA39x39-P145/X1.5 [mm]
pads (145):
  rect 1.5x1.5 hole 0.9: A1(-17.78,17.78)
  round 1.5 hole 0.9: A2(-15.24,17.78) A3(-12.7,17.78) A4(-10.16,17.78) A5(-7.62,17.78) A6(-5.08,17.78) A7(-2.54,17.78) A8(0,17.78) A9(2.54,17.78) A10(5.08,17.78) A11(7.62,17.78) A12(10.16,17.78) A13(12.7,17.78) A14(15.24,17.78) A15(17.78,17.78) B1(-17.78,15.24) B2(-15.24,15.24) B3(-12.7,15.24) B4(-10.16,15.24) B5(-7.62,15.24) B6(-5.08,15.24) B7(-2.54,15.24) B8(0,15.24) B9(2.54,15.24) B10(5.08,15.24) B11(7.62,15.24) B12(10.16,15.24) B13(12.7,15.24) B14(15.24,15.24) B15(17.78,15.24) C1(-17.78,12.7) C2(-15.24,12.7) C3(-12.7,12.7) C4(-10.16,12.7) C5(-7.62,12.7) C6(-5.08,12.7) C7(-2.54,12.7) C8(0,12.7) C9(2.54,12.7) C10(5.08,12.7) C11(7.62,12.7) C12(10.16,12.7) C13(12.7,12.7) C14(15.24,12.7) C15(17.78,12.7) D1(-17.78,10.16) D2(-15.24,10.16) D3(-12.7,10.16) D4(-10.16,10.16) D13(12.7,10.16) D14(15.24,10.16) D15(17.78,10.16) E1(-17.78,7.62) E2(-15.24,7.62) E3(-12.7,7.62) E13(12.7,7.62) E14(15.24,7.62) E15(17.78,7.62) F1(-17.78,5.08) F2(-15.24,5.08) F3(-12.7,5.08) F13(12.7,5.08) F14(15.24,5.08) F15(17.78,5.08) G1(-17.78,2.54) G2(-15.24,2.54) G3(-12.7,2.54) G13(12.7,2.54) G14(15.24,2.54) G15(17.78,2.54) H1(-17.78,0) H2(-15.24,0) H3(-12.7,0) H13(12.7,0) H14(15.24,0) H15(17.78,0) J1(-17.78,-2.54) J2(-15.24,-2.54) J3(-12.7,-2.54) J13(12.7,-2.54) J14(15.24,-2.54) J15(17.78,-2.54) K1(-17.78,-5.08) K2(-15.24,-5.08) K3(-12.7,-5.08) K13(12.7,-5.08) K14(15.24,-5.08) K15(17.78,-5.08) L1(-17.78,-7.62) L2(-15.24,-7.62) L3(-12.7,-7.62) L13(12.7,-7.62) L14(15.24,-7.62) L15(17.78,-7.62) M1(-17.78,-10.16) M2(-15.24,-10.16) M3(-12.7,-10.16) M13(12.7,-10.16) M14(15.24,-10.16) M15(17.78,-10.16) N1(-17.78,-12.7) N2(-15.24,-12.7) N3(-12.7,-12.7) N4(-10.16,-12.7) N5(-7.62,-12.7) N6(-5.08,-12.7) N7(-2.54,-12.7) N8(0,-12.7) N9(2.54,-12.7) N10(5.08,-12.7) N11(7.62,-12.7) N12(10.16,-12.7) N13(12.7,-12.7) N14(15.24,-12.7) N15(17.78,-12.7) P1(-17.78,-15.24) P2(-15.24,-15.24) P3(-12.7,-15.24) P4(-10.16,-15.24) P5(-7.62,-15.24) P6(-5.08,-15.24) P7(-2.54,-15.24) P8(0,-15.24) P9(2.54,-15.24) P10(5.08,-15.24) P11(7.62,-15.24) P12(10.16,-15.24) P13(12.7,-15.24) P14(15.24,-15.24) P15(17.78,-15.24) R1(-17.78,-17.78) R2(-15.24,-17.78) R3(-12.7,-17.78) R4(-10.16,-17.78) R5(-7.62,-17.78) R6(-5.08,-17.78) R7(-2.54,-17.78) R8(0,-17.78) R9(2.54,-17.78) R10(5.08,-17.78) R11(7.62,-17.78) R12(10.16,-17.78) R13(12.7,-17.78) R14(15.24,-17.78) R15(17.78,-17.78)
Top Overlay:
  circle w0.25: c-20.97,17.78 r0.125
  lines w0.2: -20.32,-20.32 -20.32,19.05 -19.05,20.32 20.32,20.32 20.32,-20.32 -20.32,-20.32

## PGA40X40-P145 [mm]
pads (145):
  rect 1.5x1.5 hole 0.9: A1(-17.78,17.78)
  round 1.5 hole 0.9: A2(-15.24,17.78) A3(-12.7,17.78) A4(-10.16,17.78) A5(-7.62,17.78) A6(-5.08,17.78) A7(-2.54,17.78) A8(0,17.78) A9(2.54,17.78) A10(5.08,17.78) A11(7.62,17.78) A12(10.16,17.78) A13(12.7,17.78) A14(15.24,17.78) A15(17.78,17.78) B1(-17.78,15.24) B2(-15.24,15.24) B3(-12.7,15.24) B4(-10.16,15.24) B5(-7.62,15.24) B6(-5.08,15.24) B7(-2.54,15.24) B8(0,15.24) B9(2.54,15.24) B10(5.08,15.24) B11(7.62,15.24) B12(10.16,15.24) B13(12.7,15.24) B14(15.24,15.24) B15(17.78,15.24) C1(-17.78,12.7) C2(-15.24,12.7) C3(-12.7,12.7) C4(-10.16,12.7) C5(-7.62,12.7) C6(-5.08,12.7) C7(-2.54,12.7) C8(0,12.7) C9(2.54,12.7) C10(5.08,12.7) C11(7.62,12.7) C12(10.16,12.7) C13(12.7,12.7) C14(15.24,12.7) C15(17.78,12.7) D1(-17.78,10.16) D2(-15.24,10.16) D3(-12.7,10.16) D4(-10.16,10.16) D13(12.7,10.16) D14(15.24,10.16) D15(17.78,10.16) E1(-17.78,7.62) E2(-15.24,7.62) E3(-12.7,7.62) E13(12.7,7.62) E14(15.24,7.62) E15(17.78,7.62) F1(-17.78,5.08) F2(-15.24,5.08) F3(-12.7,5.08) F13(12.7,5.08) F14(15.24,5.08) F15(17.78,5.08) G1(-17.78,2.54) G2(-15.24,2.54) G3(-12.7,2.54) G13(12.7,2.54) G14(15.24,2.54) G15(17.78,2.54) H1(-17.78,0) H2(-15.24,0) H3(-12.7,0) H13(12.7,0) H14(15.24,0) H15(17.78,0) J1(-17.78,-2.54) J2(-15.24,-2.54) J3(-12.7,-2.54) J13(12.7,-2.54) J14(15.24,-2.54) J15(17.78,-2.54) K1(-17.78,-5.08) K2(-15.24,-5.08) K3(-12.7,-5.08) K13(12.7,-5.08) K14(15.24,-5.08) K15(17.78,-5.08) L1(-17.78,-7.62) L2(-15.24,-7.62) L3(-12.7,-7.62) L13(12.7,-7.62) L14(15.24,-7.62) L15(17.78,-7.62) M1(-17.78,-10.16) M2(-15.24,-10.16) M3(-12.7,-10.16) M13(12.7,-10.16) M14(15.24,-10.16) M15(17.78,-10.16) N1(-17.78,-12.7) N2(-15.24,-12.7) N3(-12.7,-12.7) N4(-10.16,-12.7) N5(-7.62,-12.7) N6(-5.08,-12.7) N7(-2.54,-12.7) N8(0,-12.7) N9(2.54,-12.7) N10(5.08,-12.7) N11(7.62,-12.7) N12(10.16,-12.7) N13(12.7,-12.7) N14(15.24,-12.7) N15(17.78,-12.7) P1(-17.78,-15.24) P2(-15.24,-15.24) P3(-12.7,-15.24) P4(-10.16,-15.24) P5(-7.62,-15.24) P6(-5.08,-15.24) P7(-2.54,-15.24) P8(0,-15.24) P9(2.54,-15.24) P10(5.08,-15.24) P11(7.62,-15.24) P12(10.16,-15.24) P13(12.7,-15.24) P14(15.24,-15.24) P15(17.78,-15.24) R1(-17.78,-17.78) R2(-15.24,-17.78) R3(-12.7,-17.78) R4(-10.16,-17.78) R5(-7.62,-17.78) R6(-5.08,-17.78) R7(-2.54,-17.78) R8(0,-17.78) R9(2.54,-17.78) R10(5.08,-17.78) R11(7.62,-17.78) R12(10.16,-17.78) R13(12.7,-17.78) R14(15.24,-17.78) R15(17.78,-17.78)
Top Overlay:
  circle w0.25: c-22.6,17.78 r0.125
  lines w0.2: -21.95,-21.95 -21.95,20.95 -20.95,21.95 21.95,21.95 21.95,-21.95 -21.95,-21.95

## PGA40X40-P145/X1.5 [mm]
pads (145):
  rect 1.5x1.5 hole 0.9: A1(-17.78,17.78)
  round 1.5 hole 0.9: A2(-15.24,17.78) A3(-12.7,17.78) A4(-10.16,17.78) A5(-7.62,17.78) A6(-5.08,17.78) A7(-2.54,17.78) A8(0,17.78) A9(2.54,17.78) A10(5.08,17.78) A11(7.62,17.78) A12(10.16,17.78) A13(12.7,17.78) A14(15.24,17.78) A15(17.78,17.78) B1(-17.78,15.24) B2(-15.24,15.24) B3(-12.7,15.24) B4(-10.16,15.24) B5(-7.62,15.24) B6(-5.08,15.24) B7(-2.54,15.24) B8(0,15.24) B9(2.54,15.24) B10(5.08,15.24) B11(7.62,15.24) B12(10.16,15.24) B13(12.7,15.24) B14(15.24,15.24) B15(17.78,15.24) C1(-17.78,12.7) C2(-15.24,12.7) C3(-12.7,12.7) C4(-10.16,12.7) C5(-7.62,12.7) C6(-5.08,12.7) C7(-2.54,12.7) C8(0,12.7) C9(2.54,12.7) C10(5.08,12.7) C11(7.62,12.7) C12(10.16,12.7) C13(12.7,12.7) C14(15.24,12.7) C15(17.78,12.7) D1(-17.78,10.16) D2(-15.24,10.16) D3(-12.7,10.16) D4(-10.16,10.16) D13(12.7,10.16) D14(15.24,10.16) D15(17.78,10.16) E1(-17.78,7.62) E2(-15.24,7.62) E3(-12.7,7.62) E13(12.7,7.62) E14(15.24,7.62) E15(17.78,7.62) F1(-17.78,5.08) F2(-15.24,5.08) F3(-12.7,5.08) F13(12.7,5.08) F14(15.24,5.08) F15(17.78,5.08) G1(-17.78,2.54) G2(-15.24,2.54) G3(-12.7,2.54) G13(12.7,2.54) G14(15.24,2.54) G15(17.78,2.54) H1(-17.78,0) H2(-15.24,0) H3(-12.7,0) H13(12.7,0) H14(15.24,0) H15(17.78,0) J1(-17.78,-2.54) J2(-15.24,-2.54) J3(-12.7,-2.54) J13(12.7,-2.54) J14(15.24,-2.54) J15(17.78,-2.54) K1(-17.78,-5.08) K2(-15.24,-5.08) K3(-12.7,-5.08) K13(12.7,-5.08) K14(15.24,-5.08) K15(17.78,-5.08) L1(-17.78,-7.62) L2(-15.24,-7.62) L3(-12.7,-7.62) L13(12.7,-7.62) L14(15.24,-7.62) L15(17.78,-7.62) M1(-17.78,-10.16) M2(-15.24,-10.16) M3(-12.7,-10.16) M13(12.7,-10.16) M14(15.24,-10.16) M15(17.78,-10.16) N1(-17.78,-12.7) N2(-15.24,-12.7) N3(-12.7,-12.7) N4(-10.16,-12.7) N5(-7.62,-12.7) N6(-5.08,-12.7) N7(-2.54,-12.7) N8(0,-12.7) N9(2.54,-12.7) N10(5.08,-12.7) N11(7.62,-12.7) N12(10.16,-12.7) N13(12.7,-12.7) N14(15.24,-12.7) N15(17.78,-12.7) P1(-17.78,-15.24) P2(-15.24,-15.24) P3(-12.7,-15.24) P4(-10.16,-15.24) P5(-7.62,-15.24) P6(-5.08,-15.24) P7(-2.54,-15.24) P8(0,-15.24) P9(2.54,-15.24) P10(5.08,-15.24) P11(7.62,-15.24) P12(10.16,-15.24) P13(12.7,-15.24) P14(15.24,-15.24) P15(17.78,-15.24) R1(-17.78,-17.78) R2(-15.24,-17.78) R3(-12.7,-17.78) R4(-10.16,-17.78) R5(-7.62,-17.78) R6(-5.08,-17.78) R7(-2.54,-17.78) R8(0,-17.78) R9(2.54,-17.78) R10(5.08,-17.78) R11(7.62,-17.78) R12(10.16,-17.78) R13(12.7,-17.78) R14(15.24,-17.78) R15(17.78,-17.78)
Top Overlay:
  circle w0.25: c-20.9,17.78 r0.125
  lines w0.2: -20.25,-20.25 20.25,-20.25 20.25,20.25 -19.25,20.25 -20.25,19.25 -20.25,-20.25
